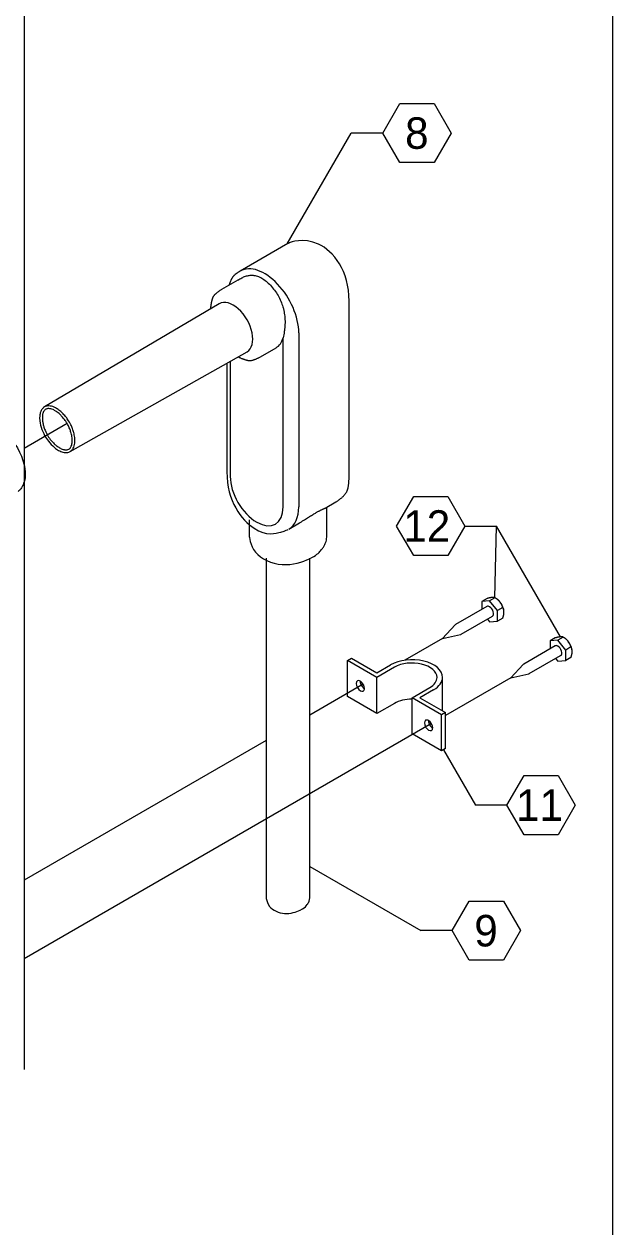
# Model space of a CAD drawing. Extents: x 99862 to 103151, y 100000 to 105076.
# Drawn here: x 102852 to 103151, y 104038 to 104648 of the extents above; entities that cross this region are included whole.
import ezdxf

# ---------------------------------------------------------------- set-up
doc = ezdxf.new("R2010")
doc.units = 0
for name, color, linetype in [('Level 1', 7, 'Continuous'), ('Level 13', 7, 'Continuous'), ('Level 15', 7, 'Continuous'), ('Level 16', 7, 'Continuous'), ('Level 20', 7, 'Continuous'), ('Level 21', 7, 'Continuous'), ('Level 27', 7, 'Continuous'), ('Level 28', 7, 'Continuous'), ('Level 31', 7, 'Continuous')]:
    doc.layers.add(name, color=color, linetype=linetype)

msp = doc.modelspace()

# ---------------------------------------------------------------- linework, layer by layer
at = {"layer": 'Level 1'}
msp.add_lwpolyline([(99862, 102999.5), (103151, 102999.5), (103151, 105075.5), (99862, 105075.5)], close=True, dxfattribs=at)
at = {"layer": 'Level 13'}
for p, q in [((102986.01, 104536.85), (102961.85, 104522.9)), ((102960.66, 104518.25), (102952.37, 104513.47)), ((103017.06, 104419.2), (103017.06, 104507.61)), ((102984.04, 104491.31), (102983.6, 104489)), ((102983.6, 104403.13), (102983.6, 104489)), ((102991.55, 104491.54), (102991.55, 104403.13)), ((102972.06, 104479.37), (102980.02, 104483.96)), ((102956.75, 104477.02), (102956.75, 104418.63)), ((102955.1, 104476.07), (102955.1, 104420.92)), ((103004.87, 104402.49), (103010.32, 104405.64)), ((103005.77, 104388.49), (103005.77, 104403.01)), ((103010.36, 104405.67), (103010.84, 104405.96)), ((103010.84, 104405.96), (103011.01, 104406.07)), ((102966.39, 104396.52), (102966.39, 104388.49)), ((102986.45, 104391.86), (102991.94, 104395.03)), ((103005.77, 104388.29), (103005.77, 104388.49))]:
    msp.add_line(p, q, dxfattribs=at)
for centre, major_axis, start_param, end_param in [((102974.15, 104501.58), (-12.3, 21.31), 3.926991, 6.282516), ((102958.24, 104494.12), (7.03, -12.18), 6.283185, 9.424778), ((102970.17, 104501.01), (9.84, -17.05), 0, 0.517335), ((102970.17, 104410.88), (9.49, -16.44), 3.926991, 7.068583), ((102974.15, 104413.17), (-12.3, 21.31), 3.140924, 3.926991)]:
    msp.add_ellipse(centre, major_axis=major_axis, ratio=0.57735, start_param=start_param, end_param=end_param, dxfattribs=at)
for points, degree in [([(103017.06, 104507.61), (103017.28, 104523.14), (103000.84, 104542.94), (102987.02, 104537.32), (102986.82, 104537.24)], 3), ([(102986.82, 104537.24), (102986.55, 104537.11), (102986.28, 104536.98), (102986.01, 104536.84)], 2), ([(102961.86, 104522.9), (102959.11, 104521.34), (102957.1, 104518.67), (102956.08, 104515.63)], 2), ([(102960.66, 104518.25), (102969.61, 104524.68), (102986.4, 104504.71), (102984.04, 104491.31)], 2), ([(102952.35, 104513.46), (102948.91, 104511.48), (102947.04, 104507.72), (102946.7, 104503.7)], 2), ([(102960.76, 104479.34), (102964.42, 104477.6), (102968.38, 104477.33), (102972.06, 104479.37)], 2), ([(102955.1, 104420.92), (102954.91, 104406.06), (102970.29, 104386.78), (102984.62, 104390.97), (102985.64, 104391.44), (102986.15, 104391.69)], 3), ([(103011.01, 104406.07), (103015.14, 104408.84), (103017.11, 104413.89), (103017.06, 104419.2)], 2), ([(102991.93, 104395.03), (102997.68, 104398.69), (103003.39, 104401.98), (103004.89, 104402.5)], 2), ([(102966.39, 104388.48), (102966.38, 104388.17), (102967.01, 104379.22), (102983.11, 104371.81), (102998.96, 104376.93), (103003.1, 104381.34), (103004.06, 104382.66), (103004.84, 104384.08), (103005.4, 104385.61), (103005.71, 104387.04), (103005.75, 104387.94), (103005.77, 104388.29)], 3)]:
    msp.add_open_spline(points, degree=degree, dxfattribs=at)
at = {"layer": 'Level 15'}
for p, q in [((102985.71, 104536.68), (103018.21, 104592.97)), ((103034.21, 104592.97), (103018.21, 104592.97)), ((103075.84, 104393.43), (103091.84, 104393.43)), ((103091.1, 104356.95), (103091.84, 104393.43)), ((103124.34, 104337.14), (103091.84, 104393.43)), ((103064.97, 104279.83), (103081.22, 104251.68)), ((103097.22, 104251.68), (103081.22, 104251.68)), ((102997.11, 104220.45), (103053.41, 104187.95)), ((102997.11, 104220.45), (103053.41, 104187.95)), ((103069.41, 104187.95), (103053.41, 104187.95)), ((103069.41, 104187.95), (103053.41, 104187.95))]:
    msp.add_line(p, q, dxfattribs=at)
at = {"layer": 'Level 16'}
for p, q in [((102873.94, 104445.45), (102852.1, 104432.84)), ((103064.56, 104336.32), (103045.37, 104325.24)), ((103024.27, 104313.06), (102997.11, 104297.38)), ((103099.18, 104316.34), (103065.96, 104297.16)), ((103058.9, 104293.08), (102852.1, 104173.68)), ((102974.97, 104284.6), (102852.1, 104213.66))]:
    msp.add_line(p, q, dxfattribs=at)
at = {"layer": 'Level 20'}
for points in [[(103034.21, 104592.97), (103042.87, 104607.96), (103060.19, 104607.96), (103068.84, 104592.97), (103060.19, 104577.97), (103042.87, 104577.97), (103034.21, 104592.97)], [(103041.22, 104393.43), (103049.88, 104408.43), (103067.2, 104408.43), (103075.84, 104393.43), (103067.2, 104378.43), (103049.88, 104378.43), (103041.22, 104393.43)], [(103097.22, 104251.68), (103105.88, 104266.68), (103123.2, 104266.68), (103131.84, 104251.68), (103123.2, 104236.68), (103105.88, 104236.68), (103097.22, 104251.68)], [(103069.41, 104187.95), (103078.07, 104202.94), (103095.39, 104202.94), (103104.03, 104187.95), (103095.39, 104172.95), (103078.07, 104172.95), (103069.41, 104187.95)]]:
    msp.add_lwpolyline(points, dxfattribs=at)
at = {"layer": 'Level 21'}
msp.add_open_spline([(102832.14, 104440.13), (102834.02, 104441.23), (102845.98, 104442.14), (102854.52, 104420.24), (102850.77, 104412.72), (102850.03, 104411.59), (102849.33, 104411.11), (102849.02, 104410.9)], degree=3, dxfattribs=at)
at = {"layer": 'Level 27'}
for p, q in [((102951.21, 104506.3), (102862.42, 104453.89)), ((102875.49, 104431.26), (102965.27, 104481.94)), ((102974.97, 104377.11), (102974.97, 104204.65)), ((102997.11, 104204.79), (102997.11, 104377.11))]:
    msp.add_line(p, q, dxfattribs=at)
for points in [[(102862.42, 104453.89), (102862.06, 104453.67), (102861.73, 104453.4), (102861.15, 104452.73), (102860.89, 104452.33), (102860.26, 104450.92), (102860.01, 104449.72), (102860.01, 104448.31)], [(102863.11, 104452.7), (102862.87, 104452.57), (102862.67, 104452.4), (102862.27, 104451.94), (102862.09, 104451.66), (102861.6, 104450.58), (102861.38, 104449.56), (102861.38, 104448.31)], [(102875.49, 104431.26), (102875.86, 104431.47), (102876.19, 104431.75), (102876.77, 104432.43), (102877.02, 104432.83), (102877.66, 104434.23), (102877.9, 104435.43), (102877.9, 104437.5), (102877.84, 104438.24), (102877.6, 104439.79), (102877.42, 104440.6), (102876.7, 104443.01), (102875.99, 104444.62), (102874.25, 104447.64), (102873.2, 104449.06), (102871.48, 104450.89), (102870.87, 104451.45), (102869.65, 104452.44), (102869.04, 104452.86), (102867.24, 104453.89), (102866.08, 104454.28), (102864.55, 104454.43), (102864.08, 104454.41), (102863.2, 104454.25), (102862.79, 104454.1), (102862.42, 104453.89)], [(102874.8, 104432.44), (102875.04, 104432.58), (102875.25, 104432.75), (102875.64, 104433.21), (102875.83, 104433.5), (102876.31, 104434.57), (102876.53, 104435.58), (102876.53, 104437.43), (102876.48, 104438.1), (102876.26, 104439.51), (102876.09, 104440.26), (102875.42, 104442.51), (102874.76, 104444.03), (102873.12, 104446.87), (102872.13, 104448.2), (102870.52, 104449.91), (102869.96, 104450.43), (102868.84, 104451.33), (102868.29, 104451.71), (102866.69, 104452.63), (102865.71, 104452.94), (102864.53, 104453.06), (102864.19, 104453.05), (102863.59, 104452.93), (102863.34, 104452.84), (102863.11, 104452.7)], [(102860.01, 104448.31), (102860.01, 104446.21), (102860.56, 104443.78), (102862.65, 104438.95), (102864.15, 104436.68), (102867.61, 104433.02), (102869.49, 104431.74), (102872.09, 104430.84), (102872.89, 104430.71), (102874.32, 104430.77), (102874.94, 104430.94), (102875.49, 104431.26)], [(102861.38, 104448.31), (102861.38, 104447.38), (102861.5, 104446.35), (102862, 104444.17), (102862.37, 104443.04), (102863.84, 104439.64), (102865.26, 104437.49), (102867.67, 104434.94), (102868.51, 104434.22), (102870.15, 104433.09), (102870.94, 104432.68), (102872.04, 104432.3), (102872.38, 104432.21), (102873, 104432.11), (102873.29, 104432.09), (102874.07, 104432.12), (102874.46, 104432.24), (102874.8, 104432.44)], [(102974.97, 104204.89), (102974.96, 104204.72), (102975.31, 104199.69), (102984.37, 104195.52), (102993.28, 104198.4), (102995.61, 104200.88), (102996.16, 104201.62), (102996.59, 104202.42), (102996.91, 104203.28), (102997.08, 104204.08), (102997.1, 104204.59), (102997.11, 104204.79)]]:
    msp.add_open_spline(points, degree=3, dxfattribs=at)
at = {"layer": 'Level 28'}
for p, q in [((103087.12, 104356.59), (103084.45, 104355.05)), ((103088.43, 104355.41), (103084.45, 104355.05)), ((103084.45, 104355.05), (103084.45, 104351.05)), ((103091.1, 104356.95), (103088.43, 104355.41)), ((103092.4, 104350.46), (103088.43, 104355.41)), ((103087.02, 104352.54), (103071.11, 104343.35)), ((103095.07, 104352), (103092.4, 104350.46)), ((103092.4, 104345.15), (103092.4, 104350.46)), ((103070.88, 104343.17), (103064.56, 104336.32)), ((103073.92, 104338.48), (103089.83, 104347.67)), ((103087.3, 104346.2), (103088.43, 104344.8)), ((103088.43, 104344.8), (103092.4, 104345.15)), ((103095.07, 104346.7), (103092.4, 104345.15)), ((103064.56, 104336.32), (103073.65, 104338.38)), ((103121.74, 104336.6), (103119.07, 104335.06)), ((103125.72, 104336.96), (103123.05, 104335.42)), ((103121.64, 104332.55), (103105.73, 104323.36)), ((103123.05, 104335.42), (103119.07, 104335.06)), ((103119.07, 104335.06), (103119.07, 104331.06)), ((103127.02, 104330.47), (103123.05, 104335.42)), ((103129.7, 104332.01), (103127.02, 104330.47)), ((103127.02, 104325.17), (103127.02, 104330.47)), ((103016.24, 104325.18), (103018.23, 104326.33)), ((103031.16, 104316.57), (103016.24, 104325.18)), ((103016.24, 104306.81), (103016.24, 104325.18)), ((103018.23, 104326.33), (103031.16, 104318.87)), ((103108.54, 104318.49), (103124.45, 104327.68)), ((103121.92, 104326.21), (103123.05, 104324.81)), ((103123.05, 104324.81), (103127.02, 104325.17)), ((103129.7, 104326.71), (103127.02, 104325.17)), ((103031.16, 104318.87), (103038.12, 104322.88)), ((103040.11, 104321.74), (103031.16, 104316.57)), ((103105.5, 104323.18), (103099.18, 104316.34)), ((103099.18, 104316.34), (103108.27, 104318.39)), ((103031.16, 104298.2), (103031.16, 104316.57)), ((103049.06, 104306.24), (103058.01, 104311.4)), ((103064.53, 104299.6), (103064.53, 104316.57)), ((103031.16, 104298.2), (103016.24, 104306.81)), ((103049.06, 104287.86), (103049.06, 104306.24)), ((103063.97, 104297.62), (103049.06, 104306.24)), ((103060, 104310.25), (103053.03, 104306.24)), ((103053.03, 104306.24), (103065.96, 104298.77)), ((103040.11, 104303.37), (103031.16, 104298.2)), ((103065.96, 104298.77), (103063.97, 104297.62)), ((103063.97, 104279.25), (103063.97, 104297.62)), ((103065.96, 104280.4), (103065.96, 104298.77)), ((103063.97, 104279.25), (103049.06, 104287.86)), ((103065.96, 104280.4), (103063.97, 104279.25))]:
    msp.add_line(p, q, dxfattribs=at)
for centre, major_axis, start_param, end_param in [((103091.71, 104352), (2.81, -4.87), 0.785398, 1.832596), ((103088.43, 104350.1), (1.41, -2.44), 2.356194, 3.141593), ((103088.43, 104350.1), (1.41, -2.44), 0, 2.356194), ((103072.52, 104340.92), (1.41, -2.44), 3.141593, 3.319303), ((103072.52, 104340.92), (1.41, -2.44), 6.105475, 6.283185), ((103123.05, 104330.11), (1.41, -2.44), 2.356194, 3.141593), ((103123.05, 104330.11), (1.41, -2.44), 6.283185, 8.63938), ((103126.33, 104332.01), (2.81, -4.87), 0.785398, 1.832596), ((103049.06, 104316.57), (15.47, 0), 0, 2.356194), ((103049.06, 104316.57), (-12.66, 0), 3.141593, 5.497787), ((103107.14, 104320.93), (1.41, -2.44), 3.141593, 3.319303), ((103107.14, 104320.93), (1.41, -2.44), 6.105475, 6.283185), ((103022.8, 104312.21), (1.48, -2.56), 3.141593, 6.283185), ((103022.8, 104312.21), (1.48, -2.56), 0.785398, 3.141593), ((103024.79, 104313.36), (-1.48, 2.56), 0.738434, 0.785398), ((103024.79, 104313.36), (-1.48, 2.56), 0.785398, 2.403158), ((103049.06, 104316.57), (-12.66, 0), 2.356194, 3.141593), ((103049.06, 104316.57), (15.47, 0), 5.497787, 6.283185), ((103022.8, 104312.21), (1.48, -2.56), 6.283185, 7.068583), ((103049.06, 104298.2), (-12.66, 0), 4.712389, 5.497787), ((103057.42, 104292.22), (1.48, -2.56), 3.141593, 6.283185), ((103057.42, 104292.22), (1.48, -2.56), 0.785398, 3.141593), ((103059.41, 104293.37), (-1.48, 2.56), 0.738434, 0.785398), ((103059.41, 104293.37), (-1.48, 2.56), 0.785398, 2.403158), ((103057.42, 104292.22), (1.48, -2.56), 0, 0.785398)]:
    msp.add_ellipse(centre, major_axis=major_axis, ratio=0.57735, start_param=start_param, end_param=end_param, dxfattribs=at)
for points in [[(103089.72, 104357.13), (103089, 104357.05), (103088.13, 104356.87), (103087.12, 104356.59)], [(103091.1, 104356.95), (103090.89, 104357.09), (103090.51, 104357.16), (103089.72, 104357.13)], [(103093.7, 104354.83), (103092.97, 104355.69), (103092.11, 104356.4), (103091.1, 104356.95)], [(103095.07, 104352), (103094.87, 104352.87), (103094.49, 104353.71), (103093.94, 104354.51)], [(103095.69, 104349.7), (103095.62, 104350.59), (103095.49, 104351.43), (103095.07, 104352)], [(103095.07, 104346.7), (103095.41, 104347.67), (103095.67, 104348.63), (103095.69, 104349.7)], [(103124.34, 104337.14), (103123.62, 104337.06), (103122.75, 104336.88), (103121.74, 104336.6)], [(103125.72, 104336.96), (103125.51, 104337.11), (103125.13, 104337.17), (103124.34, 104337.14)], [(103128.32, 104334.84), (103127.59, 104335.7), (103126.73, 104336.41), (103125.72, 104336.96)], [(103129.7, 104332.01), (103129.49, 104332.88), (103129.11, 104333.72), (103128.56, 104334.52)], [(103130.31, 104329.71), (103130.24, 104330.6), (103130.11, 104331.44), (103129.7, 104332.01)], [(103129.7, 104326.71), (103130.03, 104327.68), (103130.29, 104328.64), (103130.31, 104329.71)]]:
    msp.add_open_spline(points, degree=2, dxfattribs=at)
at = {"layer": 'Level 31'}
msp.add_line((102852.1, 104776.85), (102852.1, 104117.45), dxfattribs=at)

# ---------------------------------------------------------------- texts
at = {"layer": 'Level 20'}
for s, p in [('8', (103045.51, 104584.97)), ('12', (103044.6, 104385.43)), ('11', (103101.81, 104243.68)), ('9', (103080.63, 104179.95))]:
    msp.add_text(s, height=16, dxfattribs=at).set_placement(p)

doc.saveas('drawing.dxf')
